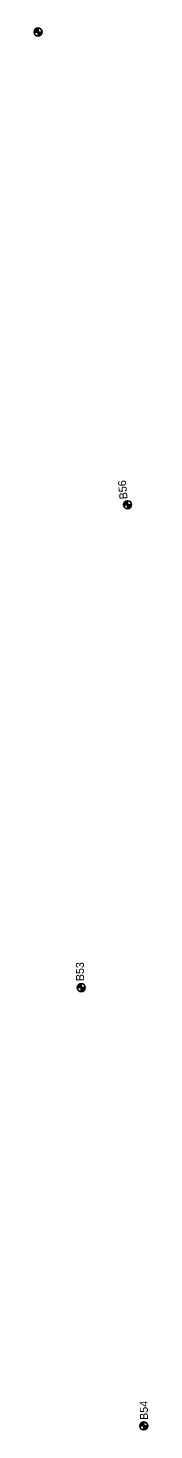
# Model space of a CAD drawing. Extents: x 331323 to 388339, y 121519 to 205315.
# Drawn here: x 360131 to 360274, y 158779 to 160532 of the extents above; entities that cross this region are included whole.
import ezdxf

# ---------------------------------------------------------------- set-up
doc = ezdxf.new("R2010")
doc.units = 0
for name, color, linetype in [('E_SOIL_BORE1 [KAPUR_CADDS_LEVELS]', 7, 'Continuous'), ('E_SOIL_BORE2 [KAPUR_CADDS_LEVELS]', 7, 'Continuous'), ('P_MARK', 7, 'Continuous')]:
    doc.layers.add(name, color=color, linetype=linetype)

msp = doc.modelspace()

# ---------------------------------------------------------------- linework, layer by layer
at = {"layer": 'P_MARK'}
for p, q in [((360131.3, 160526.6), (360141.3, 160526.6)), ((360136.3, 160531.6), (360136.3, 160521.6)), ((360248.3, 159940.8), (360248.3, 159930.8)), ((360243.3, 159935.8), (360253.3, 159935.8)), ((360185.4, 159332.2), (360195.4, 159332.2)), ((360190.4, 159337.2), (360190.4, 159327.2)), ((360263.6, 158784.4), (360273.6, 158784.4)), ((360268.6, 158789.4), (360268.6, 158779.4))]:
    msp.add_line(p, q, dxfattribs=at)
for centre in [(360136.3, 160526.6), (360248.3, 159935.8), (360190.4, 159332.2), (360268.6, 158784.4)]:
    msp.add_circle(centre, 5, dxfattribs=at)
for centre, radius, start, end in [((360136.3, 160526.6), 4.5, 89.9869, 179.9869), ((360136.3, 160526.6), 4, 89.9869, 179.9869), ((360136.3, 160526.6), 3.5, 89.9869, 179.9869), ((360136.3, 160526.6), 3, 89.9869, 179.9869), ((360136.3, 160526.6), 2.5, 89.9869, 179.9869), ((360136.3, 160526.6), 2, 89.9869, 179.9869), ((360136.3, 160526.6), 1.5, 89.9869, 179.9869), ((360136.3, 160526.6), 1, 89.9869, 179.9869), ((360136.3, 160526.6), 0.5, 89.9869, 179.9869), ((360136.3, 160526.6), 4.5, 269.9869, 359.9869), ((360136.3, 160526.6), 4, 269.9869, 359.9869), ((360136.3, 160526.6), 3.5, 269.9869, 359.9869), ((360136.3, 160526.6), 3, 269.9869, 359.9869), ((360136.3, 160526.6), 2.5, 269.9869, 359.9869), ((360136.3, 160526.6), 2, 269.9869, 359.9869), ((360136.3, 160526.6), 1.5, 269.9869, 359.9869), ((360136.3, 160526.6), 1, 269.9869, 359.9869), ((360136.3, 160526.6), 0.5, 269.9869, 359.9869), ((360248.3, 159935.8), 4.5, 89.9869, 179.9869), ((360248.3, 159935.8), 4, 89.9869, 179.9869), ((360248.3, 159935.8), 3.5, 89.9869, 179.9869), ((360248.3, 159935.8), 3, 89.9869, 179.9869), ((360248.3, 159935.8), 2.5, 89.9869, 179.9869), ((360248.3, 159935.8), 2, 89.9869, 179.9869), ((360248.3, 159935.8), 1.5, 89.9869, 179.9869), ((360248.3, 159935.8), 1, 89.9869, 179.9869), ((360248.3, 159935.8), 0.5, 89.9869, 179.9869), ((360248.3, 159935.8), 4.5, 269.9869, 359.9869), ((360248.3, 159935.8), 4, 269.9869, 359.9869), ((360248.3, 159935.8), 3.5, 269.9869, 359.9869), ((360248.3, 159935.8), 3, 269.9869, 359.9869), ((360248.3, 159935.8), 2.5, 269.9869, 359.9869), ((360248.3, 159935.8), 2, 269.9869, 359.9869), ((360248.3, 159935.8), 1.5, 269.9869, 359.9869), ((360248.3, 159935.8), 1, 269.9869, 359.9869), ((360248.3, 159935.8), 0.5, 269.9869, 359.9869), ((360190.4, 159332.2), 4.5, 89.9869, 179.9869), ((360190.4, 159332.2), 4, 89.9869, 179.9869), ((360190.4, 159332.2), 3.5, 89.9869, 179.9869), ((360190.4, 159332.2), 3, 89.9869, 179.9869), ((360190.4, 159332.2), 2.5, 89.9869, 179.9869), ((360190.4, 159332.2), 2, 89.9869, 179.9869), ((360190.4, 159332.2), 1.5, 89.9869, 179.9869), ((360190.4, 159332.2), 1, 89.9869, 179.9869), ((360190.4, 159332.2), 0.5, 89.9869, 179.9869), ((360190.4, 159332.2), 4.5, 269.9869, 359.9869), ((360190.4, 159332.2), 4, 269.9869, 359.9869), ((360190.4, 159332.2), 3.5, 269.9869, 359.9869), ((360190.4, 159332.2), 3, 269.9869, 359.9869), ((360190.4, 159332.2), 2.5, 269.9869, 359.9869), ((360190.4, 159332.2), 2, 269.9869, 359.9869), ((360190.4, 159332.2), 1.5, 269.9869, 359.9869), ((360190.4, 159332.2), 1, 269.9869, 359.9869), ((360190.4, 159332.2), 0.5, 269.9869, 359.9869), ((360268.6, 158784.4), 4.5, 89.9869, 179.9869), ((360268.6, 158784.4), 4, 89.9869, 179.9869), ((360268.6, 158784.4), 3.5, 89.9869, 179.9869), ((360268.6, 158784.4), 3, 89.9869, 179.9869), ((360268.6, 158784.4), 2.5, 89.9869, 179.9869), ((360268.6, 158784.4), 2, 89.9869, 179.9869), ((360268.6, 158784.4), 1.5, 89.9869, 179.9869), ((360268.6, 158784.4), 1, 89.9869, 179.9869), ((360268.6, 158784.4), 0.5, 89.9869, 179.9869), ((360268.6, 158784.4), 4.5, 269.9869, 359.9869), ((360268.6, 158784.4), 4, 269.9869, 359.9869), ((360268.6, 158784.4), 3.5, 269.9869, 359.9869), ((360268.6, 158784.4), 3, 269.9869, 359.9869), ((360268.6, 158784.4), 2.5, 269.9869, 359.9869), ((360268.6, 158784.4), 2, 269.9869, 359.9869), ((360268.6, 158784.4), 1.5, 269.9869, 359.9869), ((360268.6, 158784.4), 1, 269.9869, 359.9869), ((360268.6, 158784.4), 0.5, 269.9869, 359.9869)]:
    msp.add_arc(centre, radius, start, end, dxfattribs=at)

# ---------------------------------------------------------------- texts
at = {"layer": 'E_SOIL_BORE1 [KAPUR_CADDS_LEVELS]'}
for s, p in [('B53', (360193.9, 159340.4)), ('B54', (360273.9, 158792))]:
    msp.add_text(s, height=10, rotation=90.6368, dxfattribs=at).set_placement(p)
at = {"layer": 'E_SOIL_BORE2 [KAPUR_CADDS_LEVELS]'}
msp.add_text('B56', height=10, rotation=95.5802, dxfattribs=at).set_placement((360248.4, 159943.1))

doc.saveas('drawing.dxf')
